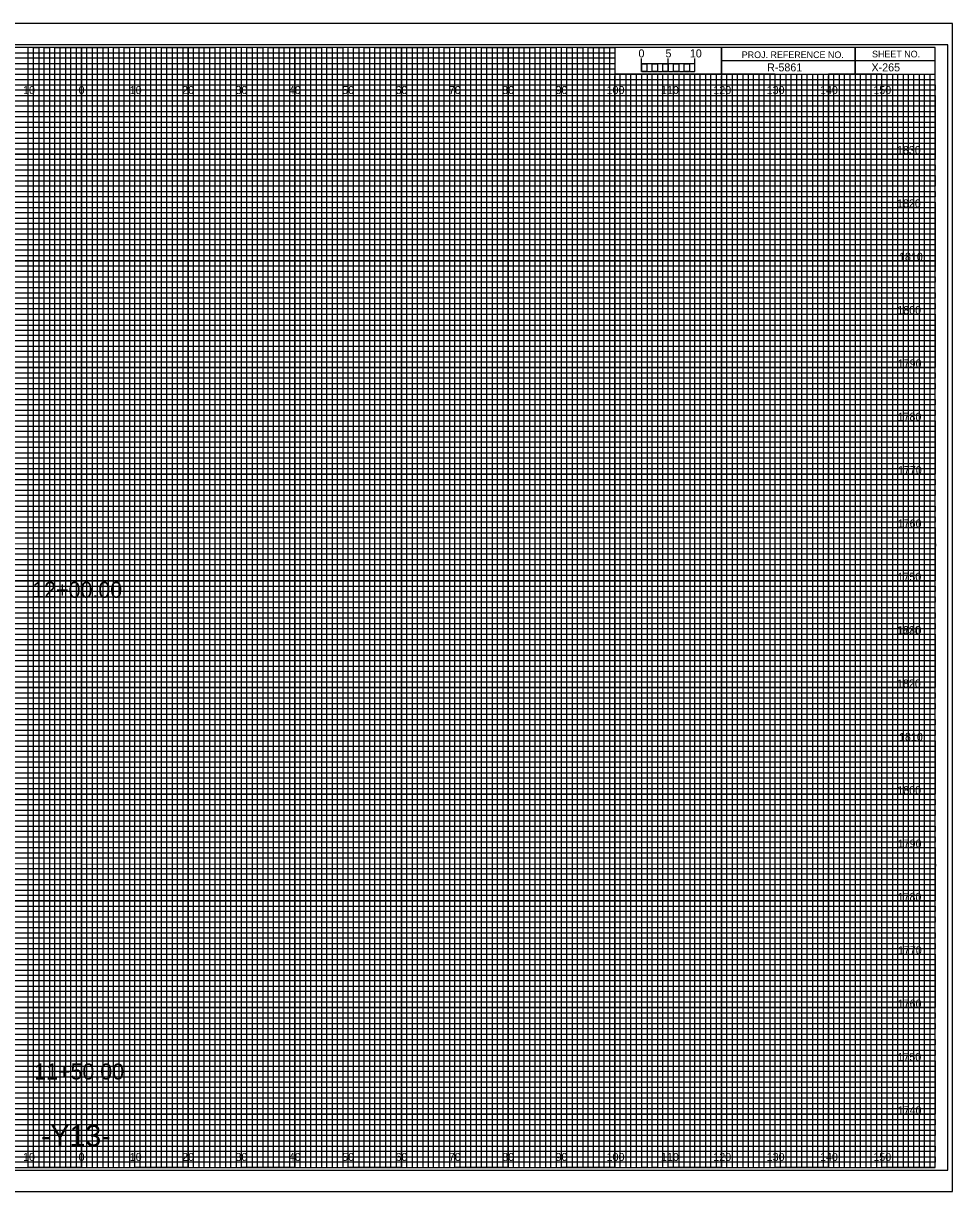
# Model space of a CAD drawing. Extents: x -13 to 323, y -5 to 654.
# Drawn here: x 149.1 to 323.3, y 215.5 to 434.5 of the extents above; entities that cross this region are included whole.
import ezdxf

# ---------------------------------------------------------------- set-up
doc = ezdxf.new("R2010")
doc.units = 0
for name, color, linetype in [('Prop Horizontal Alignment', 7, 'Continuous'), ('Prop XS Alignment Label', 7, 'Continuous'), ('Prop XS Bar Scale Labels', 7, 'Continuous'), ('Prop XS DDE', 7, 'Continuous'), ('Prop XS Earthwork Shape', 7, 'Continuous'), ('Prop XS Project Number', 7, 'Continuous'), ('Prop XS Sheet Number', 7, 'Continuous'), ('Raster_Level_0', 7, 'Continuous'), ('Scratch_Level_3', 7, 'Continuous'), ('Sheet Cross Section CELL', 7, 'Continuous'), ('Sheet Cross Section Grid Minor 1 CELL', 7, 'Continuous'), ('Sheet Cross Section Grid Minor 2 CELL', 7, 'Continuous'), ('Sheet Cross Section Scale CELL', 7, 'Continuous'), ('Sheet Cutting Line CELL', 7, 'Continuous'), ('Sheet DOT Grid CELL', 7, 'Continuous'), ('Sheet Plot Border Inside CELL', 7, 'Continuous'), ('Sheet Plot Border Outside CELL', 7, 'Continuous')]:
    doc.layers.add(name, color=color, linetype=linetype)

msp = doc.modelspace()

# ---------------------------------------------------------------- linework, layer by layer
at = {"layer": 'Prop XS DDE'}
for points in [[(145, 220), (155, 220), (155, 430), (165, 430), (165, 220), (175, 220), (175, 430), (185, 430), (185, 220), (195, 220), (195, 430), (205, 430), (205, 220), (215, 220), (215, 430), (225, 430), (225, 220), (235, 220), (235, 430), (245, 430), (245, 220), (255, 220), (255, 430), (259.93, 430), (260, 430), (260, 425), (264.99, 425), (264.99, 220), (275, 220), (275, 425), (285, 425), (285, 220), (295, 220), (295, 425), (305, 425), (305, 220), (315, 220), (315, 425)], [(0, 425), (275, 425)], [(0, 405), (320, 405), (320, 415), (0, 415)], [(0, 385), (320, 385), (320, 395), (0, 395)], [(0, 365), (320, 365), (320, 375), (0, 375)], [(0, 345), (320, 345), (320, 355), (0, 355)], [(0, 325), (320, 325), (320, 335), (0, 335)], [(0, 305), (320, 305), (320, 315), (0, 315)], [(0, 285), (320, 285), (320, 295), (0, 295)], [(0, 265), (320, 265), (320, 275), (0, 275)], [(0, 245), (320, 245), (320, 255), (0, 255)], [(0, 225), (320, 225), (320, 235), (0, 235)]]:
    msp.add_lwpolyline(points, dxfattribs=at)
at = {"layer": 'Prop XS Earthwork Shape'}
for p, q in [((150, 430), (140, 430)), ((150, 220), (150, 430)), ((170, 430), (160, 430)), ((160, 430), (160, 220)), ((170, 220), (170, 430)), ((190, 430), (180, 430)), ((180, 430), (180, 220)), ((190, 220), (190, 430)), ((210, 430), (200, 430)), ((200, 430), (200, 220)), ((210, 220), (210, 430)), ((230, 430), (220, 430)), ((220, 430), (220, 220)), ((230, 220), (230, 430)), ((250, 430), (240, 430)), ((240, 430), (240, 220)), ((250, 220), (250, 430)), ((260, 430), (260, 220)), ((270, 220), (270, 425)), ((290, 425), (280, 425)), ((280, 425), (280, 220)), ((290, 220), (290, 425)), ((310, 425), (300, 425)), ((300, 425), (300, 220)), ((310, 220), (310, 425)), ((160, 220), (150, 220)), ((180, 220), (170, 220)), ((200, 220), (190, 220)), ((220, 220), (210, 220)), ((240, 220), (230, 220)), ((260, 220), (250, 220)), ((280, 220), (270, 220)), ((300, 220), (290, 220)), ((320, 220), (310, 220)), ((320, 220), (320, 220))]:
    msp.add_line(p, q, dxfattribs=at)
for points in [[(0, 420), (320, 420), (320, 410), (0, 410)], [(0, 400), (320, 400), (320, 390), (0, 390)], [(0, 380), (320, 380), (320, 370), (0, 370)], [(0, 360), (320, 360), (320, 350), (0, 350)], [(0, 340), (320, 340), (320, 330), (0, 330)], [(0, 320), (320, 320), (320, 310), (0, 310)], [(0, 300), (320, 300), (320, 290), (0, 290)], [(0, 280), (320, 280), (320, 270), (0, 270)], [(0, 260), (320, 260), (320, 250), (0, 250)], [(0, 240), (320, 240), (320, 230), (0, 230)]]:
    msp.add_lwpolyline(points, dxfattribs=at)
at = {"layer": 'Sheet Cross Section CELL'}
for p, q in [((305, 430), (305, 425)), ((305, 425), (305, 430)), ((280, 427.5), (280, 425)), ((320, 427.49), (280, 427.49)), ((280, 425), (320, 425))]:
    msp.add_line(p, q, dxfattribs=at)
for points in [[(320, 430), (0, 430), (0, 220), (320, 220)], [(280, 430), (260, 430), (260, 425.03), (280, 425.03)], [(320, 430), (280, 430), (280, 425), (320, 425)]]:
    msp.add_lwpolyline(points, close=True, dxfattribs=at)
at = {"layer": 'Sheet Cross Section Grid Minor 1 CELL'}
for p, q in [((0, 429), (260, 429)), ((260, 427.98), (0, 427.98)), ((260, 429), (260, 427.98)), ((0, 427), (260, 427)), ((260, 425.89), (0, 425.89)), ((260, 427), (260, 425.89)), ((0, 424), (320, 424))]:
    msp.add_line(p, q, dxfattribs=at)
for points in [[(0, 423), (270, 423), (320, 423), (320, 422), (0, 422)], [(0, 421), (320, 421), (320, 419), (0, 419)], [(0, 418), (320, 418), (320, 417), (0, 416.98)], [(0, 416), (320, 416), (320, 414), (0, 414)], [(0, 413), (320, 413), (320, 412), (0, 412)], [(0, 411), (320, 411), (320, 409), (0, 409)], [(0, 408), (320, 408), (320, 407), (0, 407)], [(0, 406), (320, 406), (320, 404), (0, 404)], [(0, 403), (320, 403), (320, 402), (0, 402)], [(0, 401), (320, 401), (320, 399), (0, 399)], [(0, 398), (320, 398), (320, 397), (0, 397)], [(0, 396), (320, 396), (320, 393.95), (320, 393), (320, 392), (0, 392)], [(0, 394), (320, 394), (320, 393), (0, 393)], [(0, 391), (320, 391), (320, 389), (0, 389.03)], [(0, 389.03), (320, 389), (320, 388), (0, 388)], [(0, 387), (320, 387), (320, 386), (0, 386)], [(0, 384), (320, 384), (320, 383), (0, 383)], [(0, 382), (320, 382), (320, 381), (0, 381)], [(-0.07, 378.89), (320, 378.89), (320, 377.88), (-0.07, 377.88)], [(0, 377), (320, 377), (320, 376), (0, 376)], [(0, 374), (320, 374), (320, 373), (0, 373)], [(0, 372), (320, 372), (320, 371), (0, 371)], [(0, 369), (320, 369), (320, 368), (0, 368)], [(0, 367), (320, 367), (320, 366), (0, 366)], [(0, 364), (320, 364), (320, 363), (0, 363)], [(0, 362), (320, 362), (320, 361), (0, 361)], [(0, 359), (320, 359), (319.99, 357.98), (0, 358)], [(0, 357), (320, 357), (320, 356), (0, 356)], [(0, 354), (320, 354), (320, 353), (0, 353)], [(0, 352), (320, 352), (320, 351), (0, 351)], [(0, 349), (320, 349), (320, 348), (0, 348)], [(0, 347), (320, 347), (320, 346), (0, 346)], [(0, 344), (320, 344), (320, 343), (0, 343)], [(0, 342), (320, 342), (320, 341), (0, 341)], [(0, 339), (320, 339), (320, 338), (0, 338)], [(0, 336.99), (320.07, 336.91), (320, 336), (0, 336)], [(0, 334), (320, 334), (320, 333), (0, 333)], [(0, 332), (320, 332), (320, 331), (0, 331)], [(0, 329), (320, 329), (320, 328), (0, 328)], [(0, 327), (320, 327), (320, 326), (0, 326)], [(0, 324), (320, 324), (320, 323), (0, 323)], [(0, 322), (320, 322), (320, 321), (0, 321)], [(0, 319), (320, 319), (320, 318), (0, 318)], [(0, 317), (320, 317), (320, 316), (0, 316)], [(0, 314), (320, 314), (320, 313), (0, 313)], [(0, 312), (320, 312), (320, 311), (0, 311)], [(0, 309), (320, 309), (320, 308), (0, 308)], [(0, 307), (320, 307), (320, 306), (0, 306)], [(0, 304), (320, 304), (320, 303), (0, 303)], [(0, 302), (320, 302), (320, 301), (0, 301)], [(0, 299), (320, 299), (319.99, 297.98), (0, 298)], [(0, 297), (320, 297), (320, 296), (0, 296)], [(0, 294), (320, 294), (320, 293), (0, 293)], [(0, 292), (320, 292), (320, 291), (0, 291)], [(0, 289), (320, 289), (320, 288), (0, 288)], [(0, 287), (320, 287), (320, 286), (0, 286)], [(0, 284), (320, 284), (320, 283), (0, 283)], [(0, 282), (320, 282), (320, 281), (0, 281)], [(0, 279), (320, 279), (320, 278), (0, 278)], [(0, 276.99), (320.07, 276.91), (320, 276), (0, 276)], [(0, 274), (320, 274), (320, 273), (0, 273)], [(0, 272), (320, 272), (320, 271), (0, 271)], [(0, 269), (320, 269), (320, 268), (0, 268)], [(0, 267), (320, 267), (320, 266), (0, 266)], [(0, 264), (320, 264), (320, 263), (0, 263)], [(0, 262), (320, 262), (320, 261), (0, 261)], [(0, 259), (320, 259), (320, 258), (0, 258)], [(0, 257), (320, 257), (320, 256), (0, 256)], [(0, 254), (320, 254), (320, 253), (0, 253)], [(0, 252), (320, 252), (320, 251), (0, 251)], [(0, 249), (320, 249), (320, 248), (0, 248)], [(0, 247), (320, 247), (320, 246), (0, 246)], [(0, 244), (320, 244), (320, 243), (0, 243)], [(0, 242), (320, 242), (320, 241), (0, 241)], [(0, 239), (320, 239), (320, 238), (0, 238)], [(0, 237), (320, 237), (320, 236), (0, 236)], [(0, 234), (320, 234), (320, 233), (0, 233)], [(0, 232), (320, 232), (320, 231), (0, 231)], [(0, 229), (320, 229), (320, 228), (0, 228)], [(0, 227), (320, 227), (320, 226), (0, 226)], [(0, 224), (320, 224), (320, 223), (0, 223)], [(0, 222), (320, 222), (320, 221), (0, 221)]]:
    msp.add_lwpolyline(points, dxfattribs=at)
at = {"layer": 'Sheet Cross Section Grid Minor 2 CELL'}
for p, q in [((267, 425), (266.01, 425)), ((266.01, 425), (266.01, 220)), ((267, 220), (267, 425)), ((269, 425), (268, 425)), ((268, 425), (268, 220)), ((269, 220), (269, 425)), ((266.01, 220), (265, 220)), ((268, 220), (267, 220))]:
    msp.add_line(p, q, dxfattribs=at)
for points in [[(150, 220), (151, 220), (151, 430), (152, 430), (152, 220)], [(152, 220), (153, 220), (153, 430), (154, 430), (154, 220)], [(155, 220), (156, 220), (156, 430), (157, 430), (157, 220)], [(157, 220), (158, 220), (158, 430), (159, 430), (159, 220)], [(160, 220), (161, 220), (161, 430), (162, 430), (162, 220)], [(162, 220), (163, 220), (163, 430), (164, 430), (164, 220)], [(165, 220), (166, 220), (166, 430), (167, 430), (167, 220)], [(167, 220), (168, 220), (168, 430), (169, 430), (169, 220)], [(170, 220), (171, 220), (171, 430), (172, 430), (172, 220)], [(172, 220), (173, 220), (173, 430), (174, 430), (174, 220)], [(175, 220), (176, 220), (176, 430), (177, 430), (177, 220)], [(177, 220), (178, 220), (178, 430), (179, 430), (179, 220)], [(180, 220), (181, 220), (181, 430), (182, 430), (182, 220)], [(182, 220), (183, 220), (183, 430), (184, 430), (184, 220)], [(185, 220), (186, 220), (186, 430), (187, 430), (187, 220)], [(187, 220), (188, 220), (188, 430), (189, 430), (189, 220)], [(190, 220), (191, 220), (191, 430), (192, 430), (192, 220)], [(192, 220), (193, 220), (193, 430), (194, 430), (194, 220)], [(195, 220), (196, 220), (196, 430), (197, 430), (197, 220)], [(197, 220), (198, 220), (198, 430), (199, 430), (199, 220)], [(200, 220), (201, 220), (201, 430), (202, 430), (202, 220)], [(202, 220), (203, 220), (203, 430), (204, 430), (204, 220)], [(205, 220), (206, 220), (206, 430), (207, 430), (207, 220)], [(207, 220), (208, 220), (208, 430), (209, 430), (209, 220)], [(210, 220), (211, 220), (211, 430), (212, 430), (212, 220)], [(212, 220), (213, 220), (213, 430), (214, 430), (214, 220)], [(215, 220), (216, 220), (216, 430), (217, 430), (217, 220)], [(217, 220), (218, 220), (218, 430), (219, 430), (219, 220)], [(220, 220), (221, 220), (221, 430), (222, 430), (222, 220)], [(222, 220), (223, 220), (223, 430), (224, 430), (224, 220)], [(225, 220), (226, 220), (226, 430), (227, 430), (227, 220)], [(227, 220), (228, 220), (228, 430), (229, 430), (229, 220)], [(230, 220), (231, 220), (231, 430), (232, 430), (232, 220)], [(232, 220), (233, 220), (233, 430), (234, 430), (234, 220)], [(235, 220), (236, 220), (236, 430), (237, 430), (237, 220)], [(237, 220), (238, 220), (238, 430), (239, 430), (239, 220)], [(240, 220), (241, 220), (241, 430), (242, 430), (242, 220)], [(242, 220), (243, 220), (243, 430), (244, 430), (244, 220)], [(245, 220), (246, 220), (246, 430), (247, 430), (247, 220)], [(247, 220), (248, 220), (248, 430), (249, 430), (249, 220)], [(250, 220), (251, 220), (251, 430), (252, 430), (252, 220)], [(252, 220), (253, 220), (253, 430), (254, 430), (254, 220)], [(255, 220), (256, 220), (256, 430), (257, 430), (257, 220)], [(257, 220), (258, 220), (258, 430), (259, 430), (259, 220)], [(260, 220), (261, 220), (261, 425), (262.02, 425), (262.02, 220)], [(262, 220), (263, 220), (263, 425), (263.99, 425), (263.99, 220)], [(270, 220), (270.98, 220), (270.98, 425), (272, 425), (272, 220)], [(272, 220), (273, 220), (273, 425), (274.05, 425), (274.05, 220)], [(275, 220), (276, 220), (276, 425), (277, 425), (277, 220)], [(277, 220), (278, 220), (278, 425), (279, 425), (279, 220)], [(280, 220), (281, 220), (281, 425), (282, 425), (282, 220)], [(282, 220), (283, 220), (283, 425), (284, 425), (284, 220)], [(285, 220), (286, 220), (286, 425), (287, 425), (287, 220)], [(287, 220), (288, 220), (288, 425), (289, 425), (289, 220)], [(290, 220), (291, 220), (291, 425), (292, 425), (292, 220)], [(292, 220), (293, 220), (293, 425), (294, 425), (294, 220)], [(295, 220), (296, 220), (296, 425), (297, 425), (297, 220)], [(297, 220), (298, 220), (298, 425), (299, 425), (299, 220)], [(300, 220), (301, 220), (301, 425), (302, 425), (302, 220)], [(302, 220), (303, 220), (303, 425), (304, 425), (304, 220)], [(305, 220), (306, 220), (306, 425), (307, 425), (307, 220)], [(307, 220), (308, 220), (308, 425), (309, 425), (309, 220)], [(310, 220), (311, 220), (311, 425), (312, 425), (312, 220)], [(312, 220), (313, 220), (313, 425), (314, 425), (314, 220)], [(315, 220), (316, 220), (316, 425), (317, 425), (317, 220)], [(317, 220), (318, 220), (318, 425), (319, 425), (319, 220)]]:
    msp.add_lwpolyline(points, dxfattribs=at)
at = {"layer": 'Sheet Cross Section Scale CELL'}
for p, q in [((265, 425.49), (265, 427.9)), ((265, 426.9), (265, 427.9)), ((270, 425.49), (270, 427.9)), ((275, 425.49), (275, 427.9)), ((275, 426.9), (275, 427.9))]:
    msp.add_line(p, q, dxfattribs=at)
for points in [[(275, 426.9), (265, 426.9), (265, 425.49), (275, 425.49)], [(265, 426.9), (266, 426.9), (266, 425.49), (265, 425.49)], [(267, 426.9), (268, 426.9), (268, 425.49), (267, 425.49)], [(269, 426.9), (270, 426.9), (270, 425.49), (269, 425.49)], [(271, 426.9), (272, 426.9), (272, 425.49), (271, 425.49)], [(273, 426.9), (274, 426.9), (274, 425.49), (273, 425.49)]]:
    msp.add_lwpolyline(points, close=True, dxfattribs=at)
at = {"layer": 'Sheet Cutting Line CELL'}
for p, q in [((323.3, 434.5), (-13.4, 434.5)), ((-13.4, 215.5), (323.3, 215.5))]:
    msp.add_line(p, q, dxfattribs=at)
at = {"layer": 'Sheet DOT Grid CELL'}
for p, q in [((150, 220), (150, 430)), ((160, 220), (160, 430)), ((170, 220), (170, 430)), ((180, 220), (180, 430)), ((190, 220), (190, 430)), ((200, 220), (200, 430)), ((210, 220), (210, 430)), ((220, 220), (220, 430)), ((230, 220), (230, 430)), ((240, 220), (240, 430)), ((250, 220), (250, 430)), ((260, 220), (260, 424.69)), ((270, 220), (270, 424.69)), ((280, 220), (280, 424.69)), ((290, 220), (290, 424.69)), ((300, 220), (300, 424.69)), ((310, 220), (310, 424.69)), ((0, 420), (320, 420)), ((0, 410), (320, 410)), ((0, 400), (320, 400)), ((0, 390), (320, 390)), ((0, 380), (320, 380)), ((0, 370), (320, 370)), ((0, 360), (320, 360)), ((0, 350), (320, 350)), ((0, 340), (320, 340)), ((0, 330), (320, 330)), ((0, 320), (320, 320)), ((0, 310), (320, 310)), ((0, 300), (320, 300)), ((0, 290), (320, 290)), ((0, 280), (320, 280)), ((0, 270), (320, 270)), ((0, 260), (320, 260)), ((0, 250), (320, 250)), ((0, 240), (320, 240)), ((0, 230), (320, 230))]:
    msp.add_line(p, q, dxfattribs=at)
at = {"layer": 'Sheet Plot Border Inside CELL'}
msp.add_lwpolyline([(-10.8, 219.5), (322.4, 219.5), (322.4, 430.5), (-10.8, 430.5)], close=True, dxfattribs=at)
at = {"layer": 'Sheet Plot Border Outside CELL'}
msp.add_lwpolyline([(-13.4, 215.5), (323.3, 215.5), (323.3, 434.5), (-13.4, 434.5)], close=True, dxfattribs=at)

# ---------------------------------------------------------------- texts
at = {"layer": 'Prop Horizontal Alignment'}
for s, p in [('12+00.00', (150.77, 326.82)), ('11+50.00', (151.13, 236.52))]:
    msp.add_text(s, height=3, dxfattribs=at).set_placement(p)
at = {"layer": 'Prop XS Alignment Label'}
msp.add_text('-Y13-', height=4, dxfattribs=at).set_placement((152.39, 224))
at = {"layer": 'Prop XS Bar Scale Labels'}
for s, p in [('5', (269.47, 428.12)), ('10', (274.04, 428.12))]:
    msp.add_text(s, height=1.5, dxfattribs=at).set_placement(p)
at = {"layer": 'Prop XS Project Number'}
msp.add_text('R-5861', height=1.5, dxfattribs=at).set_placement((288.53, 425.5))
at = {"layer": 'Prop XS Sheet Number'}
msp.add_text('X-265', height=1.5, dxfattribs=at).set_placement((308.09, 425.5))
at = {"layer": 'Raster_Level_0'}
for s, p in [('10', (149.04, 421.25)), ('0', (159.45, 421.25)), ('0', (159.45, 421.25)), ('10', (169.04, 421.25)), ('20', (178.86, 421.25)), ('30', (188.86, 421.25)), ('40', (198.86, 421.25)), ('50', (208.86, 421.25)), ('60', (218.86, 421.25)), ('70', (228.86, 421.25)), ('80', (238.86, 421.25)), ('90', (248.86, 421.25)), ('100', (258.44, 421.25)), ('110', (268.62, 421.25)), ('120', (278.44, 421.25)), ('130', (288.44, 421.25)), ('140', (298.44, 421.25)), ('150', (308.44, 421.25)), ('10', (149.04, 221.25)), ('0', (159.45, 221.25)), ('0', (159.45, 221.25)), ('10', (169.04, 221.25)), ('20', (178.86, 221.25)), ('30', (188.86, 221.25)), ('40', (198.86, 221.25)), ('50', (208.86, 221.25)), ('60', (218.86, 221.25)), ('70', (228.86, 221.25)), ('80', (238.86, 221.25)), ('90', (248.86, 221.25)), ('100', (258.44, 221.25)), ('110', (268.62, 221.25)), ('120', (278.44, 221.25)), ('130', (288.44, 221.25)), ('140', (298.44, 221.25)), ('150', (308.44, 221.25))]:
    msp.add_text(s, height=1.5, dxfattribs=at).set_placement(p)
at = {"layer": 'Scratch_Level_3'}
for s, p in [('1830', (312.86, 410)), ('1820', (312.87, 400)), ('1810', (313.25, 390)), ('1800', (312.92, 380)), ('1790', (313, 370)), ('1780', (312.98, 360)), ('1770', (313.04, 350)), ('1760', (313, 340)), ('1750', (312.96, 330)), ('1830', (312.86, 320)), ('1740', (313, 320)), ('1820', (312.87, 310)), ('1810', (313.25, 300)), ('1800', (312.92, 290)), ('1790', (313, 280)), ('1780', (312.98, 270)), ('1770', (313.04, 260)), ('1760', (313, 250)), ('1750', (312.96, 240)), ('1740', (313, 230))]:
    msp.add_text(s, height=1.5, dxfattribs=at).set_placement(p)
at = {"layer": 'Sheet Cross Section CELL'}
for s, p in [('PROJ. REFERENCE NO.', (283.77, 427.99)), ('SHEET NO.', (308.19, 428.12))]:
    msp.add_text(s, height=1.25, dxfattribs=at).set_placement(p)
at = {"layer": 'Sheet Cross Section Scale CELL'}
msp.add_text('0', height=1.5, dxfattribs=at).set_placement((264.41, 428.12))

doc.saveas('drawing.dxf')
